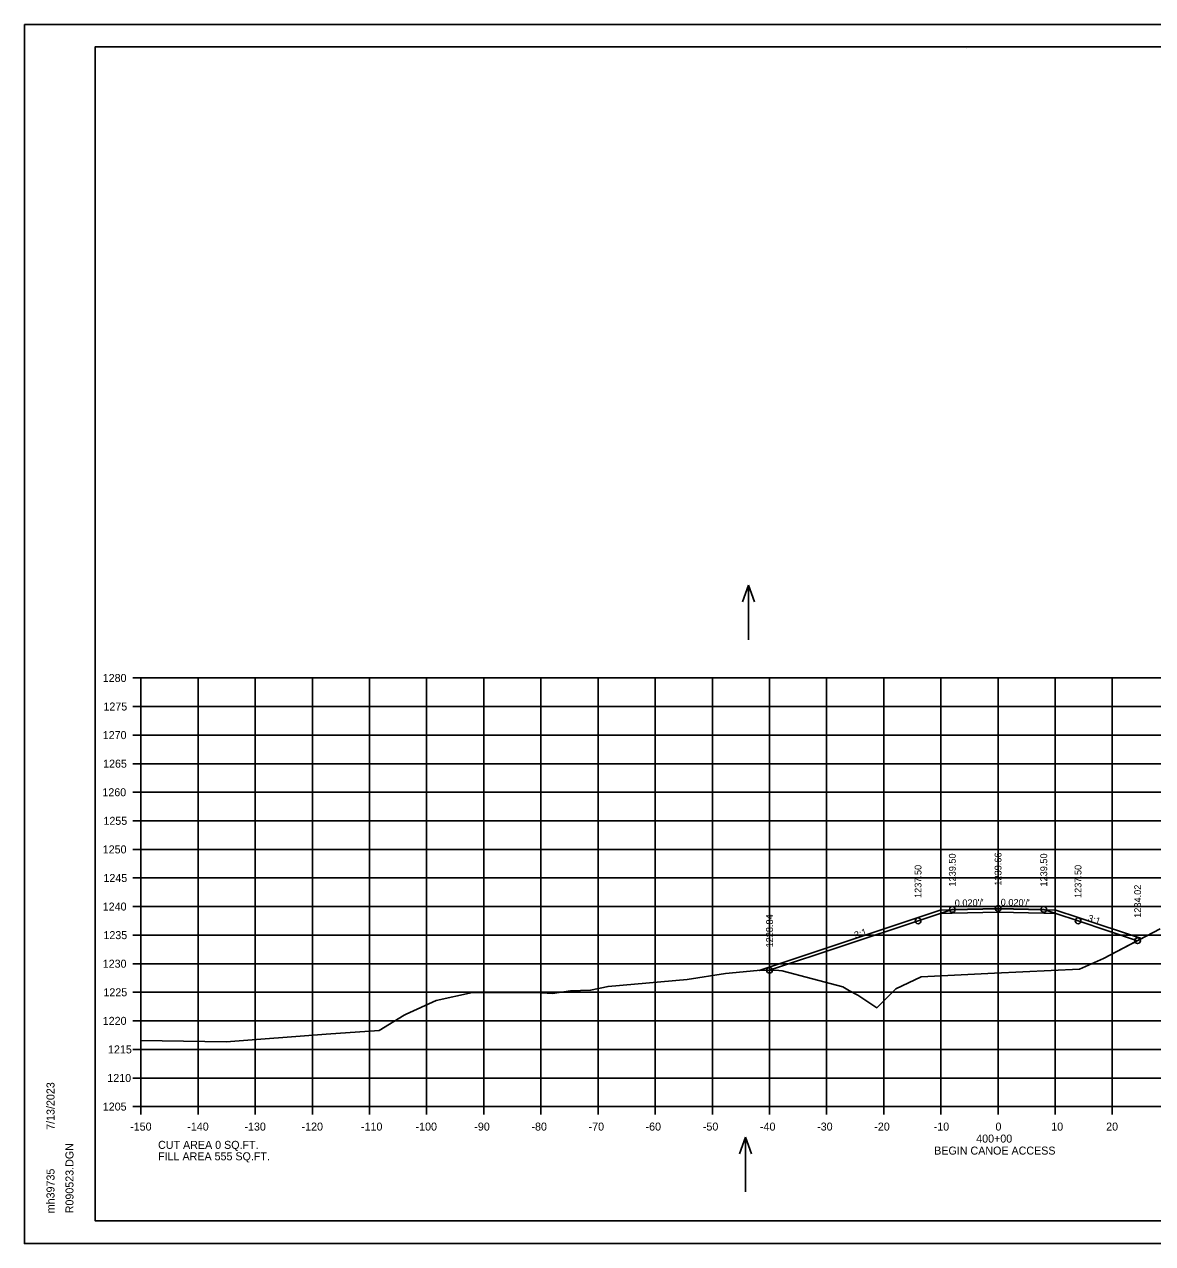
# Model space of a CAD drawing. Extents: x 1406028 to 1412453, y 321733 to 325986.
# Drawn here: x 1411612.8 to 1411810.3, y 321831.6 to 322044.9 of the extents above; entities that cross this region are included whole.
import ezdxf

# ---------------------------------------------------------------- set-up
doc = ezdxf.new("R2010")
doc.units = 0
for name, color, linetype in [('R_Alt Surface', 7, 'Continuous'), ('R_Axis', 7, 'Continuous'), ('R_Axis Annot', 7, 'Continuous'), ('R_Border', 7, 'Continuous'), ('R_Contours', 7, 'Continuous'), ('R_Exist Surface', 7, 'Continuous'), ('R_Fin Surface', 7, 'Continuous'), ('R_Fin Surface Annot', 7, 'Continuous'), ('R_Grid', 7, 'Continuous'), ('R_No Plot', 7, 'Continuous'), ('R_Water Annot', 7, 'Continuous')]:
    doc.layers.add(name, color=color, linetype=linetype)

msp = doc.modelspace()

# ---------------------------------------------------------------- linework, layer by layer
at = {"layer": 'R_Alt Surface'}
msp.add_lwpolyline([(1411773.11, 321889.36), (1411775.24, 321889.4), (1411783.24, 321889.56), (1411791.24, 321889.4), (1411793.38, 321889.36)], dxfattribs=at)
at = {"layer": 'R_Axis'}
for p, q in [((1411631.84, 321930.57), (1411633.24, 321930.57)), ((1411633.24, 321855.57), (1411633.24, 321930.57)), ((1411631.84, 321925.57), (1411633.24, 321925.57)), ((1411631.84, 321920.57), (1411633.24, 321920.57)), ((1411631.84, 321915.57), (1411633.24, 321915.57)), ((1411631.84, 321910.57), (1411633.24, 321910.57)), ((1411631.84, 321905.57), (1411633.24, 321905.57)), ((1411631.84, 321900.57), (1411633.24, 321900.57)), ((1411631.84, 321895.57), (1411633.24, 321895.57)), ((1411631.84, 321890.57), (1411633.24, 321890.57)), ((1411631.84, 321885.57), (1411633.24, 321885.57)), ((1411631.84, 321880.57), (1411633.24, 321880.57)), ((1411631.84, 321875.57), (1411633.24, 321875.57)), ((1411631.84, 321870.57), (1411633.24, 321870.57)), ((1411631.84, 321865.57), (1411633.24, 321865.57)), ((1411631.84, 321860.57), (1411633.24, 321860.57)), ((1411631.84, 321855.57), (1411633.24, 321855.57)), ((1411633.24, 321855.57), (1411933.24, 321855.57)), ((1411633.24, 321854.17), (1411633.24, 321855.57)), ((1411643.24, 321854.17), (1411643.24, 321855.57)), ((1411653.24, 321854.17), (1411653.24, 321855.57)), ((1411663.24, 321854.17), (1411663.24, 321855.57)), ((1411673.24, 321854.17), (1411673.24, 321855.57)), ((1411683.24, 321854.17), (1411683.24, 321855.57)), ((1411693.24, 321854.17), (1411693.24, 321855.57)), ((1411703.24, 321854.17), (1411703.24, 321855.57)), ((1411713.24, 321854.17), (1411713.24, 321855.57)), ((1411723.24, 321854.17), (1411723.24, 321855.57)), ((1411733.24, 321854.17), (1411733.24, 321855.57)), ((1411743.24, 321854.17), (1411743.24, 321855.57)), ((1411753.24, 321854.17), (1411753.24, 321855.57)), ((1411763.24, 321854.17), (1411763.24, 321855.57)), ((1411773.24, 321854.17), (1411773.24, 321855.57)), ((1411783.24, 321854.17), (1411783.24, 321855.57)), ((1411793.24, 321854.17), (1411793.24, 321855.57)), ((1411803.24, 321854.17), (1411803.24, 321855.57))]:
    msp.add_line(p, q, dxfattribs=at)
at = {"layer": 'R_Border'}
for p, q in [((1411625.24, 322041.03), (1411941.42, 322041.03)), ((1411625.24, 321835.57), (1411625.24, 322041.03)), ((1411777.76, 322040.77), (1411777.76, 322040.77)), ((1411777.76, 322040.77), (1411777.76, 322040.77)), ((1411625.24, 321835.57), (1411625.24, 321835.57)), ((1411941.42, 321835.57), (1411625.24, 321835.57))]:
    msp.add_line(p, q, dxfattribs=at)
at = {"layer": 'R_Contours'}
msp.add_lwpolyline([(1411741.45, 321879.4), (1411744.31, 321879.42), (1411745.48, 321879.35), (1411756.06, 321876.5), (1411757.26, 321875.83), (1411758.73, 321875.06), (1411762, 321872.87), (1411765.37, 321876.16), (1411769.81, 321878.29), (1411782.62, 321878.94), (1411797.47, 321879.59), (1411801.72, 321881.48), (1411808.36, 321884.96), (1411797.24, 321888.66), (1411793.38, 321889.95), (1411791.24, 321889.99), (1411783.24, 321890.15), (1411775.24, 321889.99), (1411773.11, 321889.95), (1411769.24, 321888.66)], close=True, dxfattribs=at)
at = {"layer": 'R_Exist Surface'}
msp.add_lwpolyline([(1411633.24, 321867.11), (1411648.17, 321866.88), (1411665.65, 321868.22), (1411674.92, 321868.88), (1411679.33, 321871.58), (1411679.53, 321871.69), (1411679.67, 321871.72), (1411684.91, 321874.12), (1411691.26, 321875.55), (1411703.34, 321875.5), (1411705.26, 321875.35), (1411708.42, 321875.85), (1411711.93, 321875.92), (1411715, 321876.6), (1411728.81, 321877.8), (1411735.52, 321878.83), (1411741.07, 321879.4), (1411744.31, 321879.42), (1411745.48, 321879.35), (1411756.06, 321876.5), (1411757.26, 321875.83), (1411758.73, 321875.06), (1411762, 321872.87), (1411765.37, 321876.16), (1411769.81, 321878.29), (1411782.62, 321878.94), (1411797.47, 321879.59), (1411801.72, 321881.48), (1411811.62, 321886.67)], dxfattribs=at)
at = {"layer": 'R_Fin Surface'}
msp.add_lwpolyline([(1411743.25, 321879.41), (1411769.24, 321888.07), (1411773.11, 321889.36), (1411775.24, 321890.07), (1411783.24, 321890.23), (1411791.24, 321890.07), (1411793.38, 321889.36), (1411797.24, 321888.07), (1411807.67, 321884.6)], dxfattribs=at)
at = {"layer": 'R_Grid'}
for p, q in [((1411633.24, 321930.57), (1411933.24, 321930.57)), ((1411633.24, 321855.57), (1411633.24, 321930.57)), ((1411643.24, 321855.57), (1411643.24, 321930.57)), ((1411653.24, 321855.57), (1411653.24, 321930.57)), ((1411663.24, 321855.57), (1411663.24, 321930.57)), ((1411673.24, 321855.57), (1411673.24, 321930.57)), ((1411683.24, 321855.57), (1411683.24, 321930.57)), ((1411693.24, 321855.57), (1411693.24, 321930.57)), ((1411703.24, 321855.57), (1411703.24, 321930.57)), ((1411713.24, 321855.57), (1411713.24, 321930.57)), ((1411723.24, 321855.57), (1411723.24, 321930.57)), ((1411733.24, 321855.57), (1411733.24, 321930.57)), ((1411743.24, 321855.57), (1411743.24, 321930.57)), ((1411753.24, 321855.57), (1411753.24, 321930.57)), ((1411763.24, 321855.57), (1411763.24, 321930.57)), ((1411773.24, 321855.57), (1411773.24, 321930.57)), ((1411783.24, 321855.57), (1411783.24, 321930.57)), ((1411793.24, 321855.57), (1411793.24, 321930.57)), ((1411803.24, 321855.57), (1411803.24, 321930.57)), ((1411633.24, 321925.57), (1411933.24, 321925.57)), ((1411633.24, 321920.57), (1411933.24, 321920.57)), ((1411633.24, 321915.57), (1411933.24, 321915.57)), ((1411633.24, 321910.57), (1411933.24, 321910.57)), ((1411633.24, 321905.57), (1411933.24, 321905.57)), ((1411633.24, 321900.57), (1411933.24, 321900.57)), ((1411633.24, 321895.57), (1411933.24, 321895.57)), ((1411633.24, 321890.57), (1411933.24, 321890.57)), ((1411633.24, 321885.57), (1411933.24, 321885.57)), ((1411633.24, 321880.57), (1411933.24, 321880.57)), ((1411633.24, 321875.57), (1411933.24, 321875.57)), ((1411633.24, 321870.57), (1411933.24, 321870.57)), ((1411633.24, 321865.57), (1411933.24, 321865.57)), ((1411633.24, 321860.57), (1411933.24, 321860.57)), ((1411633.24, 321855.57), (1411933.24, 321855.57))]:
    msp.add_line(p, q, dxfattribs=at)
at = {"layer": 'R_No Plot'}
for p, q in [((1411612.84, 322044.93), (1411946.18, 322044.93)), ((1411612.84, 321831.6), (1411946.18, 321831.6))]:
    msp.add_line(p, q, dxfattribs=at)
for points in [[(1411612.84, 322044.93), (1411946.18, 322044.93), (1411946.18, 321831.59), (1411612.84, 321831.59)], [(1411859.16, 322041.03), (1411878.78, 322041.03), (1411878.78, 322031.15), (1411894.9, 322031.15), (1411918.1, 322031.15), (1411918.1, 322006.82), (1411941.42, 322006.82), (1411941.42, 321835.57), (1411625.24, 321835.57), (1411625.24, 322041.03)]]:
    msp.add_lwpolyline(points, close=True, dxfattribs=at)
for centre in [(1411775.24, 321890.07), (1411775.24, 321890.07), (1411783.24, 321890.23), (1411791.24, 321890.07), (1411791.24, 321890.07), (1411769.24, 321888.07), (1411797.24, 321888.07), (1411807.67, 321884.6), (1411743.25, 321879.41)]:
    msp.add_circle(centre, 0.5, dxfattribs=at)
at = {"layer": 'R_Water Annot'}
for p, q in [((1411739.58, 321946.8), (1411738.51, 321943.87)), ((1411739.58, 321937.23), (1411739.58, 321946.8)), ((1411739.58, 321946.8), (1411740.64, 321943.87)), ((1411739.05, 321850.24), (1411737.98, 321847.31)), ((1411739.05, 321840.66), (1411739.05, 321850.24)), ((1411739.05, 321850.24), (1411740.11, 321847.31))]:
    msp.add_line(p, q, dxfattribs=at)

# ---------------------------------------------------------------- texts
at = {"layer": 'R_Axis Annot'}
for s, p in [('1280', (1411626.55, 321929.87)), ('1275', (1411626.67, 321924.87)), ('1270', (1411626.55, 321919.87)), ('1265', (1411626.61, 321914.87)), ('1260', (1411626.49, 321909.87)), ('1255', (1411626.67, 321904.87)), ('1250', (1411626.55, 321899.87)), ('1245', (1411626.67, 321894.87)), ('1240', (1411626.55, 321889.87)), ('1235', (1411626.67, 321884.87)), ('1230', (1411626.55, 321879.87)), ('1225', (1411626.67, 321874.87)), ('1220', (1411626.55, 321869.87)), ('1215', (1411627.47, 321864.87)), ('1210', (1411627.35, 321859.87)), ('1205', (1411626.56, 321854.87)), ('-150', (1411631.35, 321851.37)), ('-140', (1411641.35, 321851.37)), ('-130', (1411651.35, 321851.37)), ('-120', (1411661.35, 321851.37)), ('-110', (1411671.75, 321851.37)), ('-100', (1411681.3, 321851.37)), ('-90', (1411691.58, 321851.37)), ('-80', (1411701.58, 321851.37)), ('-70', (1411711.58, 321851.37)), ('-60', (1411721.55, 321851.37)), ('-50', (1411731.58, 321851.37)), ('-40', (1411741.58, 321851.37)), ('-30', (1411751.58, 321851.37)), ('-20', (1411761.58, 321851.37)), ('-10', (1411771.98, 321851.37)), ('0', (1411782.79, 321851.37)), ('10', (1411792.55, 321851.37)), ('20', (1411802.16, 321851.37)), ('400+00', (1411779.42, 321849.27)), ('CUT AREA 0 SQ.FT.', (1411636.24, 321848.17)), ('FILL AREA 555 SQ.FT.', (1411636.24, 321846.17)), ('BEGIN CANOE ACCESS', (1411772.07, 321847.17))]:
    msp.add_text(s, height=1.4, dxfattribs=at).set_placement(p)
at = {"layer": 'R_Border'}
for s, p in [('7/13/2023', (1411618.11, 321851.5)), ('R090523.DGN', (1411621.43, 321836.9)), ('mh39735', (1411618.11, 321836.9))]:
    msp.add_text(s, height=1.4, rotation=90, dxfattribs=at).set_placement(p)
at = {"layer": 'R_Fin Surface Annot'}
for s, rotation, p in [('1239.50', 90, (1411775.84, 321894.07)), ('1239.66', 90, (1411783.84, 321894.23)), ('1239.50', 90, (1411791.84, 321894.07)), ('1237.50', 90, (1411769.84, 321892.07)), ('1237.50', 90, (1411797.84, 321892.07)), ('1234.02', 90, (1411808.27, 321888.6)), ("0.020'/'", 1.1458, (1411775.67, 321890.58)), ("0.020'/'", 358.8542, (1411783.69, 321890.73)), ('1228.84', 90, (1411743.85, 321883.41)), ('3:1', 341.5651, (1411798.83, 321888.07)), ('3:1', 18.4349, (1411758.3, 321884.95))]:
    msp.add_text(s, height=1.2, rotation=rotation, dxfattribs=at).set_placement(p)

doc.saveas('drawing.dxf')
